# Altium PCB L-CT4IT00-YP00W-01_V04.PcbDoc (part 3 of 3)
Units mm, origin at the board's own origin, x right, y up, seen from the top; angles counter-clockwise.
Board outline 45 x 50 mm, 6 copper layers (Top Layer, GND1, Signal3, Siganl4, GND5, Bottom Layer), stack 1.57 mm thick; 213 components, 129 nets, 723 pads, 573 vias.
Unrouted connection lines stored in the file: 173.
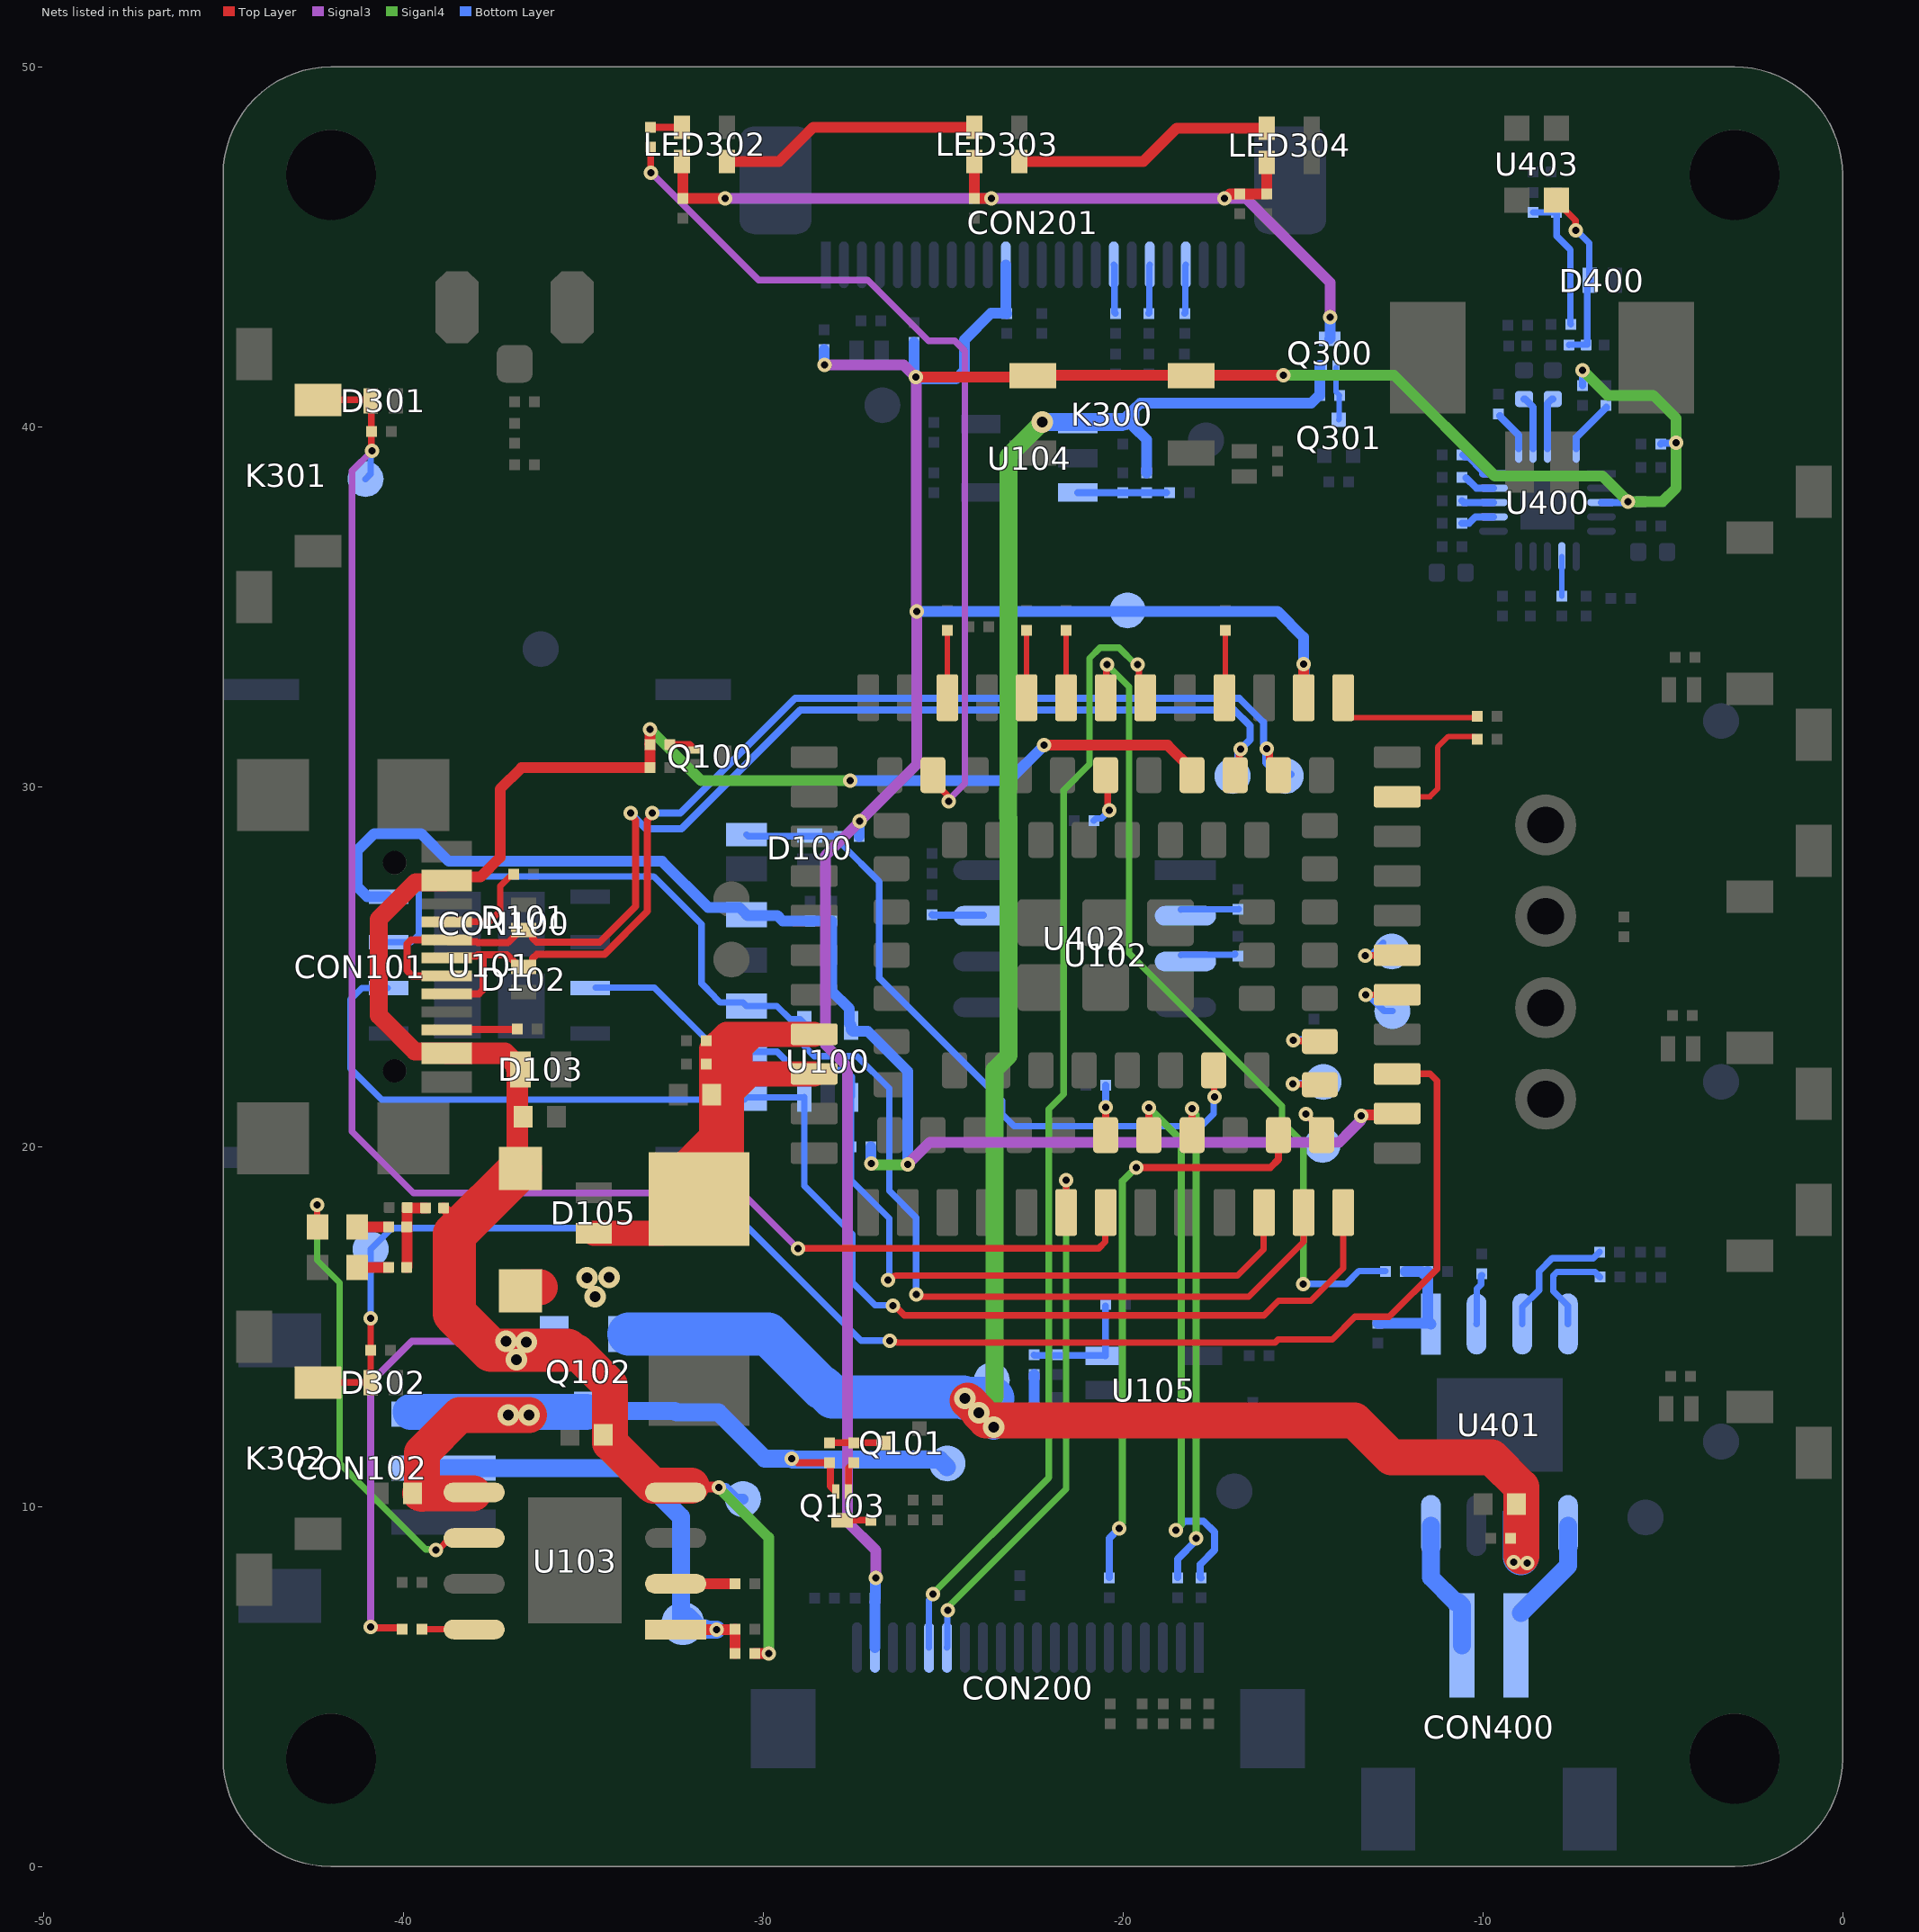
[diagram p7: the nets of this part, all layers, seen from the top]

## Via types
v1: diameter 0.4, hole 0.2, Top Layer to Bottom Layer, tented both sides, 541 vias
v2: diameter 0.6, hole 0.3, Top Layer to Bottom Layer, tented both sides, 32 vias

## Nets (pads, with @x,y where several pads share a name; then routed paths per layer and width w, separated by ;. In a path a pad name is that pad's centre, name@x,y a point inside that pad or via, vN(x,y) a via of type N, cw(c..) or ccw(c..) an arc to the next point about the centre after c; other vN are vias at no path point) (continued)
NetC410_2: C410.2 U401.2 | length 1.4
  Bottom Layer w0.18: U401.2@-10.17,15.075 -10.163,15.082 -10.163,16.054 -10.046,16.172 -10.046,16.414 -10.036,16.424 C410.2@-10.012,16.424
NetC414_1: C414.1 U400.18 | length 1.5
  Bottom Layer w0.2: U400.18@-8.2,39.4 -8.2,40.65 -8.075,40.775 C414.1@-8.05,40.775
NetC415_1: C415.1 U400.17 | length 1.5
  Bottom Layer w0.2: C415.1@-8.85,40.775 -8.825,40.775 -8.6,40.55 U400.17@-8.6,39.4
NetC416_2: C416.2 U400.16 | length 1.1
  Bottom Layer w0.2: C416.2@-9.523,40.314 -9.516,40.314 -9.516,40.285 -9,39.769 U400.16@-9,39.4
NetC417_2: C417.2 U400.15 | length 1.1
  Bottom Layer w0.2: C417.2@-10.55,39.225 -10.5,39.175 -10.401,39.175 -10,38.774 -10,38.7 U400.15@-9.7,38.7
NetC418_2: C418.2 U400.14 | length 0.9
  Bottom Layer w0.2: C418.2@-10.463,38.585 -10.178,38.3 U400.14@-9.7,38.3
NetC420_1: C420.1 R414.1 R415.2 | length 3.9
  Bottom Layer w0.18: R414.1@-8.596,45.956 C420.1@-7.946,45.956 -7.946,45.303 -7.567,44.924 -7.567,42.867 R415.2@-7.55,42.85
NetC421_2: C421.2 D400.K R412.1 U403.4 | length 4.9
  Top Layer w0.18: U403.4@-7.95,46.3 -7.69,46.04 -7.69,46 -7.421,45.731 -7.421,45.496 v1@-7.386,45.461
  Bottom Layer w0.18: R412.1@-7.6,42.275 -7.595,42.28 C421.2@-7.104,42.28 ; v1@-7.389,45.45 -7.041,45.101 D400.K@-7.041,44.08 ; C421.2@-7.096,42.288 -7.096,43.98 D400.K@-7.007,44.069
  other v1: -7.408,45.46
NetCON101_A5: CON101.A5 R108.1 | length 2.8
  Top Layer w0.18: CON101.A5@-38.787,26.25 -37.6,26.25 -37.3,26.55 -37.3,27.237 -37.022,27.515 -36.985,27.515 R108.1@-36.925,27.575
NetCON101_B5: CON101.B5 R109.1 | length 2
  Top Layer w0.2: CON101.B5@-38.787,23.25 -38.775,23.262 -36.838,23.262 R109.1@-36.825,23.275
NetCON102_2: CON102.2 R111.2 R112.1 TP104.1 U103.1 | length 13.5
  Top Layer w0.3: U103.1@-32.425,6.588 -30.787,6.588 R112.1@-30.775,6.6 R111.2@-30.775,5.925
  Bottom Layer w0.5: CON102.2@-38.875,11.075 -33.639,11.075 -32.281,9.717 -32.281,6.809 TP104.1@-32.225,6.753 ; TP104.1@-32.091,6.962 -31.907,6.778 -31.907,6.624 -31.902,6.619 -31.619,6.619 -31.582,6.582 v1(-31.288,6.582)
NetCON201_17: CON201.17 R202.2 | length 1.4
  Bottom Layer w0.18: CON201.17@-20.25,44.501 -20.231,44.482 -20.231,43.176 R202.2@-20.206,43.151
NetCON201_19: CON201.19 R203.2 | length 1.4
  Bottom Layer w0.18: R203.2@-19.281,43.151 -19.265,43.166 -19.265,44.485 CON201.19@-19.25,44.501
NetCON201_21: CON201.21 R204.2 | length 1.4
  Bottom Layer w0.18: R204.2@-18.281,43.151 -18.265,43.166 -18.265,44.485 CON201.21@-18.25,44.501
NetCON400_1: CON400.1 U401.5 | length 3
  Bottom Layer w0.5: CON400.1@-8.942,7.043 -7.63,8.355 U401.5@-7.63,9.475
NetCON400_2: CON400.2 U401.8 | length 3.7
  Bottom Layer w0.5: U401.8@-11.44,9.475 -11.44,8.03 -10.76,7.35 -10.675,7.35 -10.575,7.25 CON400.2@-10.575,6.15
NetLED300_A: LED300.A R303.1 | length 0.9
  Top Layer w0.3: LED300.A@-41.275,17.775 R303.1@-40.4,17.775
NetLED301_A: LED301.A R304.1 | length 0.9
  Top Layer w0.3: LED301.A@-41.275,16.65 R304.1@-40.4,16.65
NetLED302_2: LED302.2 R300.1 | length 0.9
  Top Layer w0.2: R300.1@-33.125,48.325 LED302.2@-32.25,48.325
NetLED302_4: LED302.4 LED303.2 | length 7.3
  Top Layer w0.3: LED302.4@-31,47.375 -29.55,47.375 -28.6,48.325 LED303.2@-24.125,48.325
NetLED303_4: LED303.4 LED304.2 | length 7.3
  Top Layer w0.3: LED303.4@-22.875,47.375 -19.425,47.375 -18.5,48.3 LED304.2@-16,48.3
NetQ100_G: Q100.G R118.1 | length 0.8
  Top Layer w0.18: R118.1@-32.592,31.175 -32.025,31.175 Q100.G@-31.875,31.025
NetQ101_C: Q101.C R121.1 R122.2 | length 1.5
  Top Layer w0.188: R121.1@-28.15,11.775 Q101.C@-26.65,11.775
NetQ103_D: Q103.D R125.2 | length 0.8
  Top Layer w0.188: Q103.D@-27.8,9.625 R125.2@-27,9.625
NetQ103_G: Q103.G R122.1 | length 0.9
  Top Layer w0.188: Q103.G@-27.625,10.425 -27.625,11.075 R122.1@-27.475,11.225
NetQ300_G: Q300.G Q301.D R305.2 | length 1.5
  Bottom Layer w0.152: Q300.G@-14.075,41.65 -14.075,40.975 R305.2@-13.975,40.875 -13.987,40.862 -13.987,40.213 Q301.D@-14,40.2
NetR103_1: R103.1 U103.8 | length 1.4
  Top Layer w0.18: R103.1@-39.444,6.594 -38.031,6.594 U103.8@-38.025,6.588
NetR104_1: R104.1 U102.33 | length 1.9
  Top Layer w0.152: U102.33@-24.875,32.475 R104.1@-24.875,34.35
NetR105_1: R105.1 U102.31 | length 1.8
  Top Layer w0.152: U102.31@-22.675,32.475 R105.1@-22.675,34.325
NetR106_1: R106.1 U102.30 | length 1.9
  Top Layer w0.152: U102.30@-21.575,32.475 R106.1@-21.575,34.35
NetR107_1: R107.1 U102.26 | length 1.9
  Top Layer w0.152: U102.26@-17.175,32.475 -17.148,32.502 R107.1@-17.148,34.35
NetR110_1: R110.1 U103.2 | length 1.6
  Top Layer w0.3: U103.2@-32.425,7.858 R110.1@-30.817,7.858
NetR114_1: R114.1 U102.49 | length 1.4
  Top Layer w0.2: U102.49@-20.475,20.325 v1(-20.475,21.1)
  Bottom Layer w0.18: v1@-20.517,21.142 v1(-20.475,21.1)
  Bottom Layer w0.2: v1(-20.475,21.1) v1(-20.475,21.1) -20.474,21.71 R114.1@-20.473,21.711
NetR115_2: R115.2 U102.50 | length 15.7
  Top Layer w0.2: v1(-19.277,21.085) v1(-19.277,21.085) U102.50@-19.275,20.325 U102.50@-19.275,20.325
  Siganl4 w0.2: v1(-19.277,21.085) -18.375,20.183 -18.375,9.498 v1(-18.522,9.351)
  Bottom Layer w0.2: v1@-19.285,21.077 v1(-19.277,21.085) ; v1@-18.509,9.371 v1@-18.502,9.371 ; v1@-18.448,9.371 v1@-18.502,9.371 ; R115.2@-17.825,8.025 -17.846,8.046 -17.846,8.398 -17.453,8.792 -17.453,9.292 -17.761,9.6 -18.273,9.6 v1@-18.502,9.371
NetR116_2: R116.2 U102.51 | length 14.1
  Top Layer w0.2: v1(-18.081,21.062) -18.078,21.059 -18.078,20.328 U102.51@-18.075,20.325
  Siganl4 w0.2: v1(-18.081,21.062) -18.081,21.007 -17.96,20.886 v1(-17.96,9.12)
  Bottom Layer w0.2: R116.2@-18.479,8.029 -18.479,8.547 -17.96,9.066 v1(-17.96,9.12) ; v1@-18.103,21.039 v1(-18.081,21.062)
NetR117_2: R117.2 U102.53 | length 16.5
  Top Layer w0.2: v1(-19.625,19.425) -15.895,19.425 -15.678,19.642 -15.678,20.322 U102.53@-15.675,20.325
  Siganl4 w0.2: v1(-20.105,9.392) -20.105,9.446 -20.01,9.541 -20.01,19.04 v1(-19.625,19.425)
  Bottom Layer w0.2: R117.2@-20.379,8.029 -20.379,9.118 v1(-20.105,9.392) v1@-20.105,9.338
NetR119_2: R119.2 U102.54 | length 1.3
  Top Layer w0.18: v1(-15.261,22.953) -15.247,22.939 -14.539,22.939 U102.54@-14.525,22.925
  Bottom Layer w0.18: v1(-15.261,22.953) -15.237,22.976 -14.712,22.976 R119.2@-14.689,23
NetR123_1: R123.1 U102.63 | length 1.6
  Top Layer w0.18: U102.63@-20.475,30.325 -20.42,30.27 -20.42,29.386 v1(-20.378,29.344)
  Bottom Layer w0.18: R123.1@-20.807,29.06 -20.747,29.12 -20.593,29.12 -20.378,29.335 v1(-20.378,29.344)
NetR127_2: R127.2 R129.2 R131.2 U104.3 | length 2.5
  Bottom Layer w0.2: U104.3@-21.25,38.175 -19.994,38.175 R131.2@-19.344,38.175 R127.2@-18.794,38.175
NetR128_2: R128.2 R130.2 R132.2 U105.3 | length 3.4
  Bottom Layer w0.18: R132.2@-22.468,14.216 -22.456,14.204 -21.818,14.204 -20.506,14.204 U105.3@-20.493,14.191 U105.3@-20.475,14.209 ; U105.3@-20.482,14.189 R128.2@-20.482,15.58
NetR133_1: R133.1 U102.22 | length 3.6
  Top Layer w0.152: U102.22@-12.375,29.725 -11.47,29.725 -11.251,29.943 -11.251,31.098 -10.952,31.397 -10.222,31.397 R133.1@-10.15,31.325
NetR134_1: R134.1 U102.23 | length 4.2
  Top Layer w0.152: U102.23@-13.875,32.475 -13.875,32.144 -13.651,31.92 -10.191,31.92 R134.1@-10.156,31.955
NetR301_1: R301.1 R302.2 R303.2 R304.2 | length 2.2
  Top Layer w0.3: R304.2@-39.9,16.65 -39.892,16.658 R303.2@-39.892,17.775 ; R303.2@-39.9,17.775 -39.883,17.792 R302.2@-39.883,18.312 -39.872,18.301 R301.1@-39.373,18.301
NetR400_2: R400.2 R401.1 R402.2 U401.1 | length 3.7
  Bottom Layer w0.3: R402.2@-12.917,15.09 U401.1@-11.455,15.09 ; R400.2@-12.147,16.534 -11.699,16.534 -11.525,16.36 ; R401.1@-11.525,16.534 -11.525,16.36 ; U401.1@-11.44,15.075 U401.1@-11.455,15.09 ; -11.525,16.36 -11.525,15.16 U401.1@-11.455,15.09
NetR406_2: R406.2 U400.7 | length 1.1
  Bottom Layer w0.152: R406.2@-7.8,35.3 U400.7@-7.8,36.4
NetR407_2: R407.2 U401.4 | length 2.9
  Bottom Layer w0.18: U401.4@-7.63,15.075 -7.63,15.58 -8.041,15.991 -8.041,16.412 -7.935,16.518 -6.882,16.518 R407.2@-6.742,16.377
NetR408_2: R408.2 U401.3 | length 3.6
  Bottom Layer w0.18: U401.3@-8.9,15.075 -8.9,15.55 -8.434,16.016 -8.434,16.533 -8.067,16.9 -6.925,16.9 R408.2@-6.75,17.075
NetR409_1: R409.1 U400.20 | length 1.5
  Bottom Layer w0.2: U400.20@-7.4,39.4 -7.4,39.7 -6.568,40.532 R409.1@-6.568,40.542
NetR410_2: R410.2 U400.13 | length 0.9
  Bottom Layer w0.2: R410.2@-10.578,37.947 -10.531,37.9 U400.13@-9.7,37.9
NetR411_2: R411.2 U400.12 | length 0.9
  Bottom Layer w0.2: R411.2@-10.575,37.325 -10.376,37.325 -10.201,37.5 U400.12@-9.7,37.5
NetR417_2: R417.2 U402.2 | length 1.6
  Bottom Layer w0.18: U402.2@-18.385,26.59 -18.38,26.595 -16.78,26.595 R417.2@-16.775,26.6
NetR418_2: R418.2 U402.3 | length 1.5
  Bottom Layer w0.18: U402.3@-18.385,25.32 -18.37,25.335 -16.89,25.335 R418.2@-16.875,25.35
NetR419_1: R419.1 U402.7 | length 1.4
  Bottom Layer w0.2: R419.1@-25.3,26.45 -25.282,26.432 U402.7@-23.878,26.432
NetTP100_1: TP100.1 U102.17 | length 1.8
  Top Layer w0.18: v1(-13.251,24.22) -13.248,24.222 U102.17@-12.378,24.222
  Bottom Layer w0.18: v1(-13.251,24.22) -13.191,24.22 -12.988,24.016 -12.979,24.016 -12.73,23.767 TP100.1@-12.508,23.767
NetTP101_1: TP101.1 U102.18 | length 1.5
  Top Layer w0.18: v1(-13.258,25.306) -13.249,25.316 U102.18@-12.384,25.316
  Bottom Layer w0.18: v1(-13.258,25.306) -13.216,25.348 -13.082,25.348 TP101.1@-12.759,25.671
NetTP105_1: TP105.1 U102.100 | length 1.8
  Top Layer w0.18: v1(-14.918,20.904) -14.911,20.904 -14.475,20.468 U102.100@-14.475,20.325
  Bottom Layer w0.18: v1(-14.918,20.904) -14.7,20.686 -14.599,20.585 -14.599,20.199 TP105.1@-14.45,20.05
NetTP106_1: TP106.1 U102.101 | length 1.6
  Top Layer w0.18: v1(-15.271,21.743) -15.262,21.734 -14.534,21.734 U102.101@-14.525,21.725
  Bottom Layer w0.18: v1(-15.271,21.743) -15.242,21.771 -14.454,21.771 TP106.1@-14.425,21.8
PA_SD: R400.1 U102.29 | length 22.8
  Top Layer w0.18: U102.29@-20.475,32.475 -20.457,32.493 -20.457,33.374 v1(-20.439,33.392)
  Siganl4 w0.18: v1(-20.439,33.392) -19.825,32.778 -19.825,25.375 -15.575,21.125 -15.575,20.687 -14.983,20.095 v1(-14.983,16.188)
  Bottom Layer w0.18: v1(-14.983,16.188) -13.796,16.188 -13.442,16.542 R400.1@-12.705,16.542
PWRKEY: C301.2 D301.K K301.3 TP301.1 U102.7 | length 46.1
  Top Layer w0.18: K301.3@-42.363,40.75 -40.925,40.75 D301.K@-40.9,40.725 -40.881,40.706 -40.881,39.352 v1(-40.862,39.333) ; v1(-29.03,17.169) -29.02,17.179 -20.667,17.179 -20.486,17.36 -20.486,18.164 U102.7@-20.475,18.175
  Signal3 w0.18: v1(-40.862,39.333) -41.42,38.775 -41.42,20.423 -39.71,18.713 -30.574,18.713 v1(-29.03,17.169)
  Bottom Layer w0.18: TP301.1@-41.043,38.548 -40.904,38.687 -40.904,39.291 v1(-40.862,39.333)
RESET: C302.2 D302.K K302.3 TP302.1 U102.15 | length 43.6
  Top Layer w0.18: K302.3@-42.363,13.45 D302.K@-40.9,13.45 C302.2@-40.9,14.35 ; C302.2@-40.901,14.351 v1(-40.902,15.23) ; v1(-26.475,14.613) -26.433,14.571 -26.278,14.571 -26.267,14.56 -15.769,14.56 -15.681,14.649 -14.176,14.649 -13.548,15.277 -12.598,15.277 -11.272,16.603 -11.272,21.831 -11.466,22.025 U102.15@-12.375,22.025
  Bottom Layer w0.18: v1(-40.902,15.23) TP302.1@-40.901,17.149 ; TP302.1@-40.9,17.15 -40.313,17.737 -30.4,17.737 -27.275,14.613 v1(-26.475,14.613)
RGB_LED: R300.2 U102.67 | length 25.1
  Top Layer w0.18: R300.2@-33.125,47.775 -33.117,47.767 -33.117,47.071 v1(-33.109,47.063) ; U102.67@-25.275,30.325 -25.275,30.167 -24.886,29.778 -24.886,29.642 v1(-24.844,29.6)
  Signal3 w0.18: v1(-33.109,47.063) -30.121,44.075 -27.089,44.075 -25.401,42.387 -24.667,42.387 -24.391,42.111 -24.391,30.084 v1@-24.875,29.6
STDBY_LED: LED300.K U103.6 | length 12.9
  Top Layer w0.18: v1(-42.385,18.384) -42.385,17.785 LED300.K@-42.375,17.775 ; v1(-39.086,8.796) -39.026,8.796 -38.695,9.128 U103.6@-38.025,9.128
  Siganl4 w0.18: v1(-42.385,18.384) -42.385,16.847 -41.762,16.224 -41.762,11.199 -39.375,8.812 -39.102,8.812 v1(-39.086,8.796)
TP_INT: CON200.15 U102.6 | length 15.3
  Top Layer w0.18: U102.6@-21.575,18.175 v1(-21.575,19.075)
  Siganl4 w0.18: v1@-24.876,7.11 -24.876,7.188 -21.575,10.489 v1(-21.575,19.075) ; v1(-24.867,7.119) v1@-24.867,7.178
  Bottom Layer w0.18: CON200.15@-24.885,6.088 -24.876,6.096 -24.876,7.11 v1(-24.867,7.119)
TP_RST: CON200.16 U102.28 | length 32
  Top Layer w0.18: v1(-19.592,33.396) -19.55,33.354 -19.55,32.65 U102.28@-19.375,32.475
  Siganl4 w0.18: v1(-25.274,7.574) -25.274,7.59 -22.059,10.804 -22.059,21.047 -21.646,21.46 -21.646,29.902 -20.923,30.625 -20.923,33.573 -20.634,33.862 -20.106,33.862 -19.64,33.396 v1(-19.592,33.396)
  Bottom Layer w0.18: CON200.16@-25.385,6.088 -25.385,7.403 -25.274,7.514 v1(-25.274,7.574)
USB_D_N: CON101.A7 CON101.B7 D101.K TP109.1 U102.60 | length 33.1
  Top Layer w0.2: CON101.A7@-38.787,24.75 -39.75,24.75 -39.889,24.889 -39.889,25.633 -39.772,25.75 CON101.B7@-38.787,25.75 -38.737,25.7 -37.963,25.7 -37.928,25.665 -37.085,25.665 D101.K@-36.8,25.95 ; D101.K@-36.65,26.025 -36.5,26.025 -36.4,25.925 -36.4,25.795 -36.283,25.677 -34.539,25.677 -33.538,26.679 -33.538,29.075 -33.675,29.212 v1(-33.675,29.266) ; U102.60@-16.875,30.325 -16.763,30.437 -16.763,31.012 v1(-16.725,31.05)
  Bottom Layer w0.2: v1(-33.675,29.266) -33.675,29.262 -33.249,28.836 -32.264,28.836 -28.967,32.133 -16.905,32.133 -16.466,31.694 -16.466,31.309 v1(-16.725,31.05) -16.725,30.996 -16.797,30.924 -16.797,30.405 TP109.1@-16.664,30.272 ; TP109.1@-16.95,30.3 TP109.1@-16.797,30.453
USB_D_P: CON101.A6 CON101.B6 D102.K TP110.1 U102.59 | length 32.5
  Top Layer w0.2: CON101.B6@-38.787,24.25 -37.892,24.25 -37.775,24.367 -37.775,25.31 -37.75,25.335 ; CON101.A6@-38.787,25.25 -38.737,25.3 -37.963,25.3 -37.928,25.335 -37.75,25.335 ; D102.K@-36.825,25.05 -37.11,25.335 -37.75,25.335 ; D102.K@-36.65,25 -36.5,25 -36.4,25.1 -36.4,25.23 -36.283,25.347 -34.403,25.347 -33.208,26.542 -33.208,29.075 -33.071,29.212 v1(-33.071,29.266) ; v1(-15.997,31.052) -15.997,30.998 -15.922,30.923 -15.922,30.572 U102.59@-15.675,30.325
  Bottom Layer w0.2: v1(-33.071,29.266) -32.301,29.266 -29.103,32.463 -16.768,32.463 -16.094,31.789 -16.094,31.203 -15.997,31.106 v1(-15.997,31.052) -16.023,31.027 -16.023,30.673 -15.7,30.35 TP110.1@-15.325,30.35
USIM_CLK: CON100.3 U100.3 U101.6 U102.13 | length 37.9
  Top Layer w0.18: v1(-26.393,15.577) -26.333,15.577 -26.07,15.314 -16.077,15.314 -15.673,15.718 -14.774,15.718 -13.875,16.617 U102.13@-13.875,18.175
  Bottom Layer w0.18: U101.6@-40.425,24.41 -41.143,24.41 -41.462,24.091 -41.462,22.177 -40.592,21.307 -30.521,21.307 CON100.3@-30.457,21.37 -28.855,21.37 U100.3@-28.85,21.375 -28.85,18.912 -27.51,17.571 -27.51,16.225 -26.882,15.597 -26.413,15.597 v1(-26.393,15.577)
USIM_DATA: CON100.7 R101.1 U100.1 U101.3 U102.11 | length 26
  Top Layer w0.18: v1(-26.529,16.3) -26.47,16.3 -26.36,16.41 -26.325,16.41 -26.314,16.421 -16.811,16.421 -16.086,17.147 -16.086,18.164 U102.11@-16.075,18.175
  Bottom Layer w0.18: U101.3@-34.645,24.423 -33.019,24.423 -31.288,22.693 -30.51,22.693 CON100.7@-30.457,22.64 -29.607,22.64 -29.092,22.125 -27.713,22.125 -27.525,21.937 U100.1@-27.525,21.4 ; U100.1@-27.55,21.375 -27.55,20.15 -27.55,19.069 -26.491,18.01 -26.491,16.339 v1(-26.529,16.3)
USIM_DET: CON100.CD D100.K R100.2 U102.79 | length 19.7
  Top Layer w0.18: U102.79@-17.475,22.125 -17.463,22.113 -17.463,21.399 v1(-17.451,21.387)
  Bottom Layer w0.18: CON100.CD@-30.457,28.67 -30.412,28.625 -28.7,28.625 R100.2@-27.875,28.625 -27.815,28.565 -27.815,28.406 -26.77,27.361 -26.77,24.688 -23.358,21.277 -23.358,20.907 -23.022,20.57 -17.819,20.57 -17.475,20.914 v1@-17.475,21.469
USIM_RST: CON100.2 U100.4 U101.7 U102.12 | length 37.5
  Top Layer w0.18: v1(-25.742,15.901) -25.671,15.83 -16.503,15.83 -14.973,17.36 -14.973,18.173 U102.12@-14.975,18.175
  Bottom Layer w0.18: U101.7@-40.425,25.68 -39.776,25.68 -39.559,25.897 -39.559,27.134 -39.184,27.509 -33.034,27.509 -31.708,26.183 -31.708,24.537 -31.35,24.179 -31.35,24.167 -31.187,24.004 -30.552,24.004 CON100.2@-30.457,23.91 -29.61,23.91 -29.241,23.541 -28.96,23.541 -28.85,23.431 U100.4@-28.85,23.375 -28.85,22.796 -28.568,22.514 -27.387,22.514 -26.491,21.618 -26.491,18.778 -25.742,18.029 v1(-25.742,15.901)
USIM_VDD: C100.2 C101.2 CON100.1 R101.2 U100.5 U101.8 U102.14 | length 40
  Top Layer w0.3: v1(-26.993,19.529) v1@-26.974,19.51 ; v1@-25.992,19.495 v1(-25.974,19.513) ; v1(-13.37,20.864) -13.35,20.883 -12.417,20.883 U102.14@-12.375,20.925
  Signal3 w0.3: v1(-25.974,19.513) -25.362,20.125 -13.986,20.125 -13.662,20.449 -13.662,20.454 -13.389,20.728 -13.389,20.844 v1(-13.37,20.864)
  Siganl4 w0.3: v1@-26.974,19.495 v1@-25.992,19.495
  Bottom Layer w0.3: U101.8@-40.425,26.95 -41,26.95 -41.275,27.225 -41.275,28.225 -40.8,28.7 -39.5,28.7 -38.729,27.929 -32.804,27.929 -31.525,26.65 -30.658,26.65 CON100.1@-30.457,26.45 -30.431,26.424 -29.601,26.424 -29.452,26.275 C101.2@-28.688,26.275 C100.2@-28.088,26.275 ; C100.2@-28.091,26.272 -28.091,24.327 -27.6,23.836 -27.6,23.425 U100.5@-27.55,23.375 -27.55,23.256 -27.5,23.206 -27.083,23.206 -25.978,22.1 v1@-25.978,19.516 ; R101.2@-27.003,19.994 -27.003,19.539 v1(-26.993,19.529)
VBAT: C102.1 C103.2 C104.2 C105.2 C113.2 C114.2 C411.1 C412.2 D104.K D105.K Q102.S Q300.S R131.1 R132.1 R305.1 TP111.1 U102.42 U102.43 U104.1 U105.1 U401.6 | length 97.3
  Top Layer w0.7: D105.K@-34.702,17.598 -32.827,17.598 -31.875,18.55 C102.1@-31.775,18.55 C102.1@-31.388,18.938 ; C102.1@-32.612,19.112 -31.425,20.299 ; U102.43@-28.575,22.025 -30.35,22.025 ; U102.42@-28.575,23.125 -30.25,23.125 ; -31.425,20.299 C103.2@-31.425,21.45 -31.425,22.715 -31.015,23.125 -30.65,23.125 ; -31.425,20.299 -31.425,18.975 C102.1@-31.388,18.938 ; C102.1@-31.388,18.938 -30.875,19.45 -30.875,21.5 ; -30.875,21.5 -30.35,22.025 ; -30.875,21.5 -30.875,22 ; -30.875,22 -30.875,22.5 ; -30.875,22 -30.85,22.025 ; -30.875,22.5 -30.638,22.738 ; -30.875,22.5 -30.875,22.9 -30.65,23.125 ; -30.85,22.025 -30.638,22.237 -30.638,22.738 ; -30.85,22.025 -30.35,22.025 ; -30.65,23.125 -30.25,23.125 ; -30.638,22.738 -30.25,23.125
  Top Layer w1: D104.K@-36.742,15.998 -36.642,16.098 D104.K@-36.203,16.098 ; v2@-24.312,12.949 v2@-23.983,12.62 ; v2(-24,12.603) -23.797,12.4 -13.568,12.4 -12.534,11.366 -9.746,11.366 -8.925,10.545 -8.925,8.621
  Siganl4 w0.5: v2(-24.383,13.01) v2@-24.355,13.01 ; v2(-24,12.603) v2@-23.981,12.622 ; v2(-23.584,12.204) -23.584,12.622 v2@-23.981,12.622 ; -23.584,13.046 -23.981,12.649 v2@-23.981,12.622 ; -23.564,13.046 -23.564,22.141 -23.175,22.53 -23.175,29.131 -23.184,29.141 -23.184,29.938 -23.175,29.947 -23.175,39.189 v2(-22.233,40.131)
  Bottom Layer w0.3: -22.493,12.291 -22.468,12.316 R132.1@-22.468,13.666 ; C113.2@-20.042,40.132 -19.689,40.485 ; C113.2@-20.027,40.131 -19.827,40.131 -19.689,39.993 ; R131.1@-19.344,38.725 -19.344,39.648 -19.689,39.993 ; -14.525,41.707 R305.1@-14.525,40.875 -14.546,40.875 -14.758,40.663 -19.511,40.663 -19.689,40.485 ; -19.689,39.993 -19.689,40.485
  Bottom Layer w0.5: v2(-22.233,40.131) C113.2@-20.027,40.131
  Bottom Layer w0.7: v2(-23.584,12.204) v2@-23.496,12.291 ; v2@-23.471,12.316 v2@-23.496,12.291 ; U105.1@-20.493,12.291 -22.493,12.291 v2@-23.496,12.291
  Bottom Layer w1: -8.936,8.593 U401.6@-8.936,9.805
  Bottom Layer w1.2: Q102.S@-33.726,14.8 -29.864,14.8 -28.364,13.3 ; -28.345,13.32 -28.067,13.042 v2@-24.439,13.042 ; v2(-24.383,13.01) -23.61,13.01
  other v1: -8.757,8.437 -9.137,8.462
  other v2: -34.657,15.831 -34.888,16.355 -34.276,16.367
VBAT_Li: C111.2 CON102.3 Q102.D Q103.S R121.2 TP107.1 U103.5 | length 23.5
  Top Layer w0.2: v1(-29.205,11.334) -29.151,11.334 -29.042,11.225 R121.2@-28.15,11.225 -28.123,11.198 -28.123,10.566 Q103.S@-28.012,10.455
  Top Layer w1: C111.2@-39.531,10.367 C111.2@-39.481,10.367 ; C111.2@-39.481,10.355 C111.2@-39.481,10.367 ; U103.5@-38.056,10.367 C111.2@-39.481,10.367 ; v2(-36.5,12.55) v2(-37.075,12.55) -38.425,12.55 -39.481,11.494 C111.2@-39.481,10.367
  Bottom Layer w0.5: Q102.D@-34.85,12.7 -34.81,12.66 -32.446,12.66 -32.406,12.62 -31.239,12.62 -29.953,11.334 v1(-29.205,11.334) -29.177,11.306 -25.094,11.306 TP107.1@-24.888,11.1
  Bottom Layer w1: CON102.3@-39.79,12.637 -37.075,12.637 Q102.D@-34.913,12.637
VBUS: C106.2 CON101.A4B9 CON101.B4A9 D103.K D104.A Q102.G R103.2 R111.1 R113.2 R118.2 R124.2 R301.2 TP108.1 U102.61 U103.4 | length 71.4
  Top Layer w0.2: v1(-40.903,6.657) -40.875,6.628 -40.053,6.628 R103.2@-40.025,6.6
  Top Layer w0.3: R301.2@-38.873,18.301 -38.575,18.003 -38.575,17.565 ; CON101.A4B9@-38.692,27.495 -37.846,27.495 -37.303,28.038 -37.303,29.935 -36.711,30.527 R113.2@-33.142,30.527 R118.2@-33.142,31.175 ; R118.2@-33.15,31.183 R118.2@-33.142,31.175 ; v1(-33.135,31.591) -33.142,31.583 R118.2@-33.142,31.175 ; U103.4@-31.985,10.582 -31.911,10.582 -31.875,10.546 -31.248,10.546 v1(-31.229,10.527) ; R111.1@-30.225,5.925 -29.851,5.925 v1(-29.842,5.916) ; v1(-22.182,31.155) -18.755,31.155 -18.075,30.475 U102.61@-18.075,30.325
  Top Layer w0.5: CON101.A4B9@-38.837,27.35 -39.65,27.35 -40.675,26.325 -40.675,23.65 -39.675,22.65 -38.837,22.65 CON101.B4A9@-38.819,22.631
  Top Layer w0.6: CON101.B4A9@-38.787,22.6 -37.175,22.6 D103.K@-36.85,22.275 ; D103.K@-36.835,22.15 -36.825,22.14 -36.825,19.675 D104.A@-36.675,19.525
  Top Layer w1: -35.175,14.3 -34.25,13.375 -34.25,11.775 -33.057,10.582 U103.4@-31.985,10.582
  Top Layer w1.2: D104.A@-36.742,19.398 -38.575,17.565 -38.575,15.364 -37.551,14.34 -35.439,14.34
  Signal3 w0.2: v1@-40.9,6.725 -40.9,13.45 -39.749,14.601 v2(-37.143,14.601)
  Siganl4 w0.3: v1(-33.135,31.591) -31.715,30.171 v1@-27.577,30.171 ; v1(-31.229,10.527) -29.842,9.14 v1(-29.842,5.916)
  Bottom Layer w0.3: v1(-31.229,10.527) -31.21,10.508 -31.041,10.508 -30.743,10.209 TP108.1@-30.553,10.209 ; v1(-27.577,30.172) -23.165,30.172 v1(-22.182,31.155)
  other v2: -36.846,14.083 -36.579,14.572
VCC_RGB: C306.1 C307.1 C308.1 C309.1 LED302.3 LED303.3 LED304.3 Q300.D | length 25.1
  Top Layer w0.3: LED302.3@-32.25,47.375 -32.225,47.35 C306.1@-32.225,46.35 v1(-31.05,46.35) ; LED303.3@-24.125,47.375 C309.1@-24.125,46.35 -23.66,46.35 v1(-23.654,46.345) ; v1(-17.175,46.349) -17.148,46.349 -17.021,46.475 C307.1@-16.75,46.475 ; C307.1@-16.725,46.475 C308.1@-16,46.475 LED304.3@-16,47.35
  Signal3 w0.3: v1(-31.05,46.35) -31.047,46.347 -23.657,46.347 v1(-23.654,46.345) -23.652,46.347 -17.178,46.347 -17.175,46.35 -16.579,46.35 -14.232,44.002 v1(-14.232,43.045)
  Bottom Layer w0.3: Q300.D@-14.25,42.45 -14.241,42.459 -14.241,43.036 v1(-14.232,43.045)
VDD_EXT: C109.2 C202.1 C212.1 C404.1 CON200.19 CON201.11 K300.3 K300.4 R100.1 R200.2 R201.2 R403.2 R404.2 TP306.1 U102.24 U400.3 | length 89.6
  Top Layer w0.3: v1(-25.749,41.377) -25.74,41.387 -22.538,41.387 K300.4@-22.5,41.425 -22.496,41.429 -18.1,41.429 -18.099,41.43 -15.539,41.43 v1(-15.535,41.435) ; v1(-14.977,33.402) -14.976,33.401 -14.976,32.476 U102.24@-14.975,32.475
  Signal3 w0.3: v1(-28.293,41.716) -26.089,41.716 v1(-25.749,41.377) ; v1(-26.862,8.026) -26.862,8.787 -27.655,9.58 -27.655,22.222 -28.269,22.836 -28.269,28.082 v1(-27.309,29.042) -25.72,30.63 -25.72,34.866 v1(-25.727,34.873) -25.738,34.884 -25.738,41.366 v1@-25.727,41.377
  Siganl4 w0.3: v1(-15.535,41.435) -12.467,41.435 -9.664,38.632 -6.67,38.632 v1(-5.96,37.922) -5.003,37.922 -4.623,38.302 v1(-4.623,39.559) -4.623,40.237 -5.26,40.874 -6.525,40.874 -7.197,41.546 v1@-7.197,41.573
  Bottom Layer w0.2: R403.2@-7.225,41.15 v1(-7.225,41.575) ; U400.3@-6.7,37.9 -5.982,37.9 v1(-5.96,37.922) -5.959,37.923 -5.602,37.923 C404.1@-5.6,37.925 ; R404.2@-5.05,39.525 -5.033,39.542 -4.64,39.542 v1(-4.623,39.559)
  Bottom Layer w0.3: R200.2@-28.306,42.151 -28.306,41.73 v1(-28.293,41.716) ; R100.1@-27.325,28.625 -27.325,29.026 v1(-27.309,29.042) ; CON200.19@-26.885,6.087 C202.1@-26.885,7.36 ; C202.1@-26.881,7.46 -26.881,8.007 v1(-26.862,8.026) ; R201.2@-25.807,42.35 -25.807,41.461 -25.749,41.404 v1(-25.749,41.377) -25.73,41.358 -25.659,41.358 -25.632,41.331 -24.636,41.331 -24.401,41.566 -24.401,42.418 -23.667,43.152 C212.1@-23.246,43.152 ; v1(-25.727,34.873) -15.698,34.873 -14.977,34.152 v1(-14.977,33.402) -14.958,33.383 -14.958,32.908 C109.2@-14.95,32.9 ; CON201.11@-23.25,44.501 -23.25,43.17 C212.1@-23.231,43.151
pads on no net: BadMARK.2 CON100.0@-32.942,27.46 CON100.0@-36.967,22.38 CON100.0@-36.967,24.92 CON100.0@-36.967,27.46 CON100.0@-42.942,22.38 CON100.0@-42.942,24.92 CON100.0@-42.942,27.46 CON100.6 CON101. CON101.A8 CON101.B8 CON201.1 CON201.6 CON201.7 CON201.9 CON201.10 CON201.12 CON201.14 CON201.16 CON201.18 CON201.20 CON201.22 CON201.23 CON201.24 D100. D101. D102. D103. D105. D200. D300. D301. D302. D303. D304. D305. D400. H300.1 H301.1 H302.1 H303.1 LED304.4 Oil300.29 Q102. U101. U101.0 U101.2 U101.4 U101.5 U102.2 U102.3 U102.4 U102.8 U102.9 U102.44 U102.65 U102.68 U102.69 U102.74 U102.75 U102.76 U102.77 U102.83 U102.84 U102.85 U102.86 U102.98 U102.99 U102.102 U102.104 U102.105 U102.106 U102.107 U102.108 U102.109 U103. U400. U401. U402.

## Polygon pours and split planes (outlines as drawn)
GND on GND5 "T-G" (solid, remove dead copper, pour order 11): -43.016,0 cw(c-43.016,2) -45.016,2 -45.016,48 cw(c-43.016,48) -43.016,50 -2.016,50 cw(c-2.016,48) -0.016,48 -0.016,2 cw(c-2.016,2) -2.016,0
AGND on GND5 "G4-AGND" (solid, remove dead copper, pour order 2): -5.686,36.689 -5.686,38.034 -2.45,41.27 -2.45,45.52 -5.568,48.638 -10.462,48.638 -10.85,48.25 -10.85,44 -12.475,42.375 -12.475,35.949 -11.519,34.993 -7.382,34.993 -5.875,36.5
GND on Signal3 "T-G" (solid, remove dead copper, pour order 6): -43.016,0 cw(c-43.016,2) -45.016,2 -45.016,48 cw(c-43.016,48) -43.016,50 -2.016,50 cw(c-2.016,48) -0.016,48 -0.016,2 cw(c-2.016,2) -2.016,0
GND on Siganl4 "T-G" (solid, remove dead copper, pour order 7): -43,0 cw(c-43,2) -45,2 -45,48 cw(c-43,48) -43,50 -2,50 cw(c-2,48) 0,48 0,2 cw(c-2,2) -2,0
GND on Top Layer "T-G" (solid, remove dead copper, pour order 4): -43,0 cw(c-43,2) -45,2 -45,48 cw(c-43,48) -43,50 -2,50 cw(c-2,48) 0,48 0,2 cw(c-2,2) -2,0
GND on GND1 "T-G" (solid, remove dead copper, pour order 5): -43.016,0 cw(c-43.016,2) -45.016,2 -45.016,48 cw(c-43.016,48) -43.016,50 -2.016,50 cw(c-2.016,48) -0.016,48 -0.016,2 cw(c-2.016,2) -2.016,0
GND on Bottom Layer "T-G" (solid, remove dead copper, pour order 12): -43.016,0 cw(c-43.016,2) -45.016,2 -45.016,48 cw(c-43.016,48) -43.016,50 -2.016,50 cw(c-2.016,48) -0.016,48 -0.016,2 cw(c-2.016,2) -2.016,0
AGND on Bottom Layer "G4-AGND" (solid, remove dead copper, pour order 10): -5.686,36.689 -5.686,38.034 -2.45,41.27 -2.45,45.52 -5.568,48.638 -10.462,48.638 -10.85,48.25 -10.85,44 -12.475,42.375 -12.475,35.949 -11.519,34.993 -7.382,34.993 -5.875,36.5

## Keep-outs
Keep-Out Layer:
  the board outline again, w0.127

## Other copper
Top Layer:
  pour cut-out: -16.626,23.765 -16.626,23.233 -16.548,23.155 -16.26,23.155 -16.26,23.769 -16.654,23.769
  pour cut-out: -13.403,23.203 -13.935,23.203 -14.013,23.125 -14.013,22.837 -13.4,22.837 -13.4,23.231
  pour cut-out: -18.896,31.321 -18.896,31.853 -18.974,31.931 -19.263,31.931 -19.263,31.317 -18.868,31.317
  pour cut-out: -23.025,27.925 -22.96,27.86 -18.709,27.86 -18.709,27.991 -18.375,28.325 -18.375,30.075 -19.311,31.011 -25.52,31.011 -25.52,30.412 -24.433,29.325 -23.834,29.325 -23.025,28.515
  pour cut-out: -11.582,27.723 -11.582,28.255 -11.66,28.333 -11.949,28.333 -11.949,27.719 -11.554,27.719
  pour cut-out: -15.939,30.147 -16.471,30.147 -16.549,30.069 -16.549,29.781 -15.935,29.781 -15.935,30.175
  pour cut-out: -37.825,16.49 -37.409,16.49 -37.409,16.713 -37.385,16.738 -37.434,16.788 -37.825,16.788 -37.825,16.532 -37.793,16.501
  pour cut-out: -41.895,16.12 -41.894,16.119 -41.467,16.119 -41.467,18.275 -41.496,18.304 -42.058,18.304 -42.058,16.305 -41.885,16.131
  pour cut-out: -39.727,16.321 -39.312,16.321 -39.312,16.545 -39.287,16.569 -39.337,16.619 -39.727,16.619 -39.727,16.364 -39.695,16.332
  pour cut-out: -28.846,26.668 -28.846,27.2 -28.923,27.278 -29.334,27.278 -29.334,26.703 -29.369,26.668 -29.366,26.665 -28.818,26.665
  pour cut-out: -25.525,19.01 -19.7,19.01 -19.7,17.889 -25.364,17.889 -25.525,18.05
  region net VBUS: -38.078,22.612 -37.497,22.03 -37.493,22.03 -37.493,18.818 -37.325,18.65 -36.175,18.65 -35.992,18.833 -35.992,20.058 -36.257,20.323 -36.257,22.626 -36.527,22.897 -37.793,22.897
  region net VBAT: -37.35,15.575 -37.175,15.4 -34.55,15.4 -32.33,17.62 -32.33,18.83 -32.612,19.112 -33.099,19.112 -34.12,18.091 -35.209,18.091 -36.5,16.8 -37.15,16.8 -37.35,16.6
Signal3:
  region net VBAT: -24.721,13.129 -24.721,12.671 -23.906,11.856 -23.442,11.856 -23.283,12.015 -23.283,12.635 -24.022,13.374 -24.476,13.374
Siganl4:
  pour cut-out: -15.234,25.639 -15.207,25.666 -14.699,25.666 -14.699,25.39 -14.827,25.263 -14.912,25.347 -15.22,25.347 -15.22,25.625
  pour cut-out: -19.304,33.684 -19.3,33.688 -18.821,33.688 -18.821,33.248 -18.866,33.203 -18.877,33.214 -19.431,33.214 -19.431,33.632 -19.378,33.684
  region net VBAT: -24.721,13.129 -24.721,12.671 -23.906,11.856 -23.442,11.856 -23.286,12.012 -23.286,13.107 -23.553,13.374 -24.476,13.374
Bottom Layer:
  rectangle net GND: -3.408,42.25 -1.5,43.15
  rectangle: -39.512,2.265 -30.912,5.14
  pour cut-out: -28.711,23.888 -28.711,23.625 -28.031,23.625 -28.008,23.602 -27.959,23.652 -27.959,24.213 -28.387,24.213
  pour cut-out: -16.495,29.851 -16.49,29.846 -15.931,29.846 -15.931,30.128 -15.927,30.131 -15.985,30.189 -16.445,30.189 -16.445,29.897 -16.496,29.846
  pour cut-out: -39.659,24.27 -39.657,24.268 -39.657,23.286 -40.213,23.286 -40.309,23.383 -40.309,24.285 -39.682,24.285 -39.659,24.262
  pour cut-out: -22.907,25.117 -22.905,25.115 -22.905,24.133 -23.461,24.133 -23.558,24.229 -23.558,25.132 -22.93,25.132 -22.907,25.109
  pour cut-out: -22.84,27.584 -22.838,27.582 -22.838,26.6 -23.393,26.6 -23.49,26.697 -23.49,27.6 -22.863,27.6 -22.84,27.577
  pour cut-out: -19.354,27.519 -19.381,27.493 -19.381,25.37 -18.133,25.37 -18.097,25.335 -18.075,25.357 -18.075,27.675 -19.202,27.675 -19.381,27.496
  pour cut-out: -31.137,22.414 -31.137,21.639 -31.05,21.552 -30.689,21.552 -30.689,22.431 -30.707,22.414
  pour cut-out: -31.202,23.732 -31.202,22.957 -31.116,22.871 -30.755,22.871 -30.755,23.75 -30.772,23.732
  region net VBAT: -24.721,13.129 -24.721,12.758 -23.819,11.856 -23.24,11.856 -22.618,12.477 -22.618,12.544 -23.448,13.374 -24.476,13.374
  region net VBUS: -37.45,15.175 -37.45,14.025 -37.15,13.725 -35.725,13.725 -35.225,14.225 -35.225,15.05 -35.6,15.425 -37.2,15.425
  region net VBAT: -35.25,15.95 -33.953,14.653 -32.541,14.653 -32.122,15.071 -32.122,15.347 -33.475,16.7 -35,16.7 -35.25,16.45
Multi-Layer:
  pour cut-out: -42,0.5 cw(c-42,3) -44.5,3 cw(c-42,3) -42,5.5 cw(c-42,3) -39.5,3 cw(c-42,3)
  pour cut-out: -3,0.5 cw(c-3,3) -5.5,3 cw(c-3,3) -3,5.5 cw(c-3,3) -0.5,3 cw(c-3,3)
  pour cut-out: -3,44.5 cw(c-3,47) -5.5,47 cw(c-3,47) -3,49.5 cw(c-3,47) -0.5,47 cw(c-3,47)
  pour cut-out: -42,44.5 cw(c-42,47) -44.5,47 cw(c-42,47) -42,49.5 cw(c-42,47) -39.5,47 cw(c-42,47)

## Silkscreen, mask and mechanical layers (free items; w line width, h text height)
Top Overlay:
  circle w0.127: c-3,3 r2.5
  circle w0.127: c-15.375,47.85 r3.5
  circle w0.127: c-31.625,47.85 r3.5
  circle w0.127: c-23.5,47.85 r3.5
  circle w0.127: c-42,47 r2.5
  circle w0.127: c-3,47 r2.5
  circle w0.127: c-42,3 r2.5
  text "RGB0" at -33.1,44.675 h1.5
  text "RGB1" at -24.975,44.675 h1.5
  text "RGB2" at -16.85,44.65 h1.5
  text "MIC_N" at -13.6,38.309 h1.5
  text "MIC_P" at -6.458,38.309 h1.5
  text "BOOT" at -21.875,37.425 h1.5
  text "PWRKEY" at -40.261,34.431 h1.5 r90
  text "KEY2" at -3.7,34.24 h1.5 r90
  text "KEY1" at -3.7,24.265 h1.5 r90
  text "KEY0" at -3.7,14.29 h1.5 r90
  text "RESET" at -40.339,5.698 h1.5 r90
  text "S/C" at -23.575,3.478 h1.3
  text "YYWW" at -24.375,2.248 h1.3
  text "L-CT4IT00-YP00W-01_V04" at -28.75,0.8 h1.4
Bottom Overlay:
  text "GND" at -9.303,28.55 h1.5
  text "3V3" at -9.556,26.01 h1.5
  text "SCL" at -9.517,23.47 h1.5
  text "SDA" at -9.285,20.965 h1.5
  text "+" at -36.892,13.55 h2.2
  text "_" at -36.736,8.3 h2.2
  text "SPK" at -11.925,7.3 h1.5
Bottom Solder:
  drawing of 7 lines, arcs and shapes, not listed
Mechanical 1:
  circle w0.254: c-8.5,47.3 r3
  lines w0.1: -47.237,11.5 -43.338,11.5 ; -47.237,38.5 -43.338,38.5 ; -22.5,-3.75 -22.5,50 ; -22.5,0 -22.5,5.275 ; -3.9,15.025 0,15.025 ; -3.9,25 0,25 ; -3.9,35.975 0,35.975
